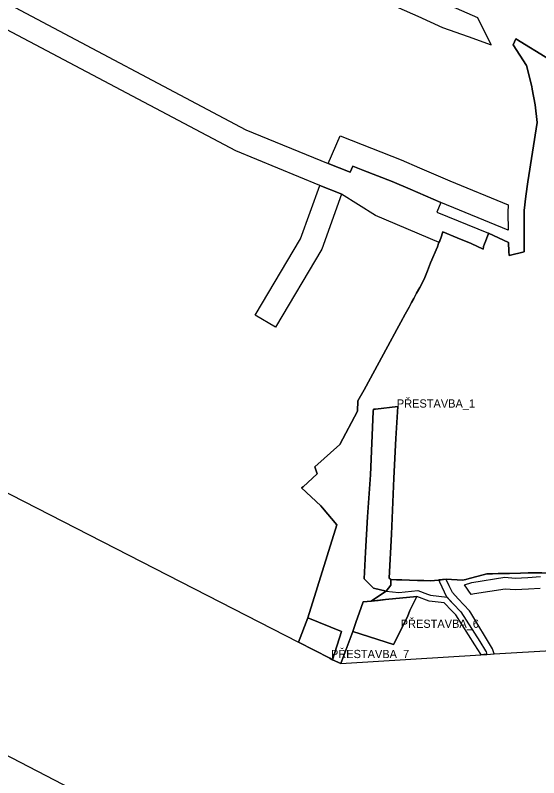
# Model space of a CAD drawing. Extents: x -521621 to -516761, y -1190184 to -1184927.
# Drawn here: x -520400 to -519954, y -1187593 to -1186944 of the extents above; entities that cross this region are included whole.
import ezdxf

# ---------------------------------------------------------------- set-up
doc = ezdxf.new("R2010")
doc.units = 0
for name, color, linetype in [('hran_SZUO_P-s', 7, 'Continuous'), ('HZU_P_s', 7, 'Continuous'), ('Implicitní', 7, 'Continuous'), ('prestavba_n', 7, 'Continuous'), ('zastavitelne plochy', 7, 'Continuous')]:
    doc.layers.add(name, color=color, linetype=linetype)

msp = doc.modelspace()

# ---------------------------------------------------------------- linework, layer by layer
at = {"layer": 'hran_SZUO_P-s'}
for points in [[(-519973.89, -1186964.34), (-519976.25, -1186969.59)], [(-519945.18, -1186982.09), (-519973.89, -1186964.34)], [(-519976.25, -1186969.59), (-519964.74, -1186987.19)], [(-519964.74, -1186987.19), (-519960.28, -1187004.95)], [(-519960.28, -1187004.95), (-519959.86, -1187007.38)], [(-519959.86, -1187007.38), (-519957.58, -1187020.75)], [(-519957.58, -1187020.75), (-519955.72, -1187035.72)], [(-519955.72, -1187035.72), (-519963.72, -1187086.02)], [(-519963.72, -1187086.02), (-519965.26, -1187098.25), (-519966.79, -1187110.48)], [(-519966.79, -1187110.48), (-519966.76, -1187125.1), (-519966.72, -1187139.73)], [(-520036.08, -1187128.81), (-520037.66, -1187134.14)], [(-520023.97, -1187133.79), (-520036.08, -1187128.81)], [(-519997.52, -1187130.94), (-519998.64, -1187133.89), (-519999.75, -1187136.84)], [(-519997.15, -1187129.97), (-519997.34, -1187130.46), (-519997.52, -1187130.94)], [(-519980.11, -1187137.79), (-519988.63, -1187133.88), (-519997.15, -1187129.97)], [(-520039.62, -1187138.78), (-520040.71, -1187141.36)], [(-520037.66, -1187134.14), (-520039.62, -1187138.78)], [(-520011.85, -1187138.77), (-520023.97, -1187133.79)], [(-520001.85, -1187143.49), (-520011.85, -1187138.77)], [(-519999.75, -1187136.84), (-520000.58, -1187139.01), (-520001.4, -1187141.18)], [(-519979.8, -1187145.46), (-519980.11, -1187137.79)], [(-519966.72, -1187139.73), (-519966.71, -1187142.68), (-519966.7, -1187145.62)], [(-520041.85, -1187144.05), (-520045.46, -1187152.58)], [(-520040.71, -1187141.36), (-520041.85, -1187144.05)], [(-520001.4, -1187141.18), (-520001.85, -1187143.49)], [(-519979.66, -1187148.75), (-519979.8, -1187145.46)], [(-519966.7, -1187145.62), (-519979.66, -1187148.75)], [(-520045.46, -1187152.58), (-520046.54, -1187155.01)], [(-520046.54, -1187155.01), (-520049.24, -1187161.96)], [(-520049.24, -1187161.96), (-520051.52, -1187167.64)], [(-520052.48, -1187170.02), (-520055.75, -1187176.08)], [(-520051.52, -1187167.64), (-520052.48, -1187170.02)], [(-520055.75, -1187176.08), (-520058.38, -1187180.94)], [(-520060.79, -1187185.41), (-520062.6, -1187188.74)], [(-520058.38, -1187180.94), (-520060.79, -1187185.41)], [(-520062.6, -1187188.74), (-520064.75, -1187192.74)], [(-520064.75, -1187192.74), (-520068.02, -1187198.79)], [(-520068.02, -1187198.79), (-520071.75, -1187205.69)], [(-520071.75, -1187205.69), (-520075.16, -1187212)], [(-520075.16, -1187212), (-520082.78, -1187226.03)], [(-520082.78, -1187226.03), (-520103.06, -1187263.21)], [(-520103.06, -1187263.21), (-520108.49, -1187272.64)], [(-520108.49, -1187272.64), (-520108.69, -1187281.29)], [(-520108.69, -1187281.29), (-520123.82, -1187309.68)], [(-520123.82, -1187309.68), (-520145.11, -1187328.82)], [(-520143.11, -1187334.68), (-520154.87, -1187345.66)], [(-520145.11, -1187328.82), (-520143.11, -1187334.68)], [(-520154.87, -1187345.66), (-520156.34, -1187346.76)], [(-520156.34, -1187346.76), (-520139.86, -1187362)], [(-520139.86, -1187362), (-520138.59, -1187363.54)], [(-520138.59, -1187363.54), (-520126.44, -1187378.2)], [(-520126.44, -1187378.2), (-520151.11, -1187457.31)], [(-519969.88, -1187419.22), (-519963.38, -1187419.06), (-519956.87, -1187418.91)], [(-519956.87, -1187418.91), (-519951.65, -1187419.02), (-519946.42, -1187419.12)], [(-520080.41, -1187429.63), (-520080.26, -1187424.69)], [(-520080.26, -1187424.69), (-520075.65, -1187424.83), (-520071.03, -1187424.98)], [(-520071.03, -1187424.98), (-520064.4, -1187425.2), (-520057.77, -1187425.41)], [(-520057.77, -1187425.41), (-520052.12, -1187425.59), (-520046.46, -1187425.77)], [(-520046.46, -1187425.77), (-520039.87, -1187425.11)], [(-520039.87, -1187425.11), (-520033.27, -1187424.46)], [(-520033.27, -1187424.46), (-520019.29, -1187425.32)], [(-520019.29, -1187425.32), (-520016.5, -1187424.59)], [(-520016.5, -1187424.59), (-520013.71, -1187423.87)], [(-520013.71, -1187423.87), (-520006.09, -1187421.89), (-519998.46, -1187419.91)], [(-519998.46, -1187419.91), (-519993.68, -1187419.8), (-519988.89, -1187419.68)], [(-519988.89, -1187419.68), (-519979.39, -1187419.45), (-519969.88, -1187419.22)], [(-520084.35, -1187434.57), (-520080.41, -1187429.63)], [(-520090.73, -1187438.81), (-520084.35, -1187434.57)], [(-520097.11, -1187443.05), (-520090.73, -1187438.81)], [(-520084.9, -1187441.83), (-520091.01, -1187442.44), (-520097.11, -1187443.05)], [(-520058.07, -1187439.16), (-520084.9, -1187441.83)], [(-520064.09, -1187451.2), (-520058.07, -1187439.16)], [(-520066.25, -1187456.45), (-520064.09, -1187451.2)], [(-520151.11, -1187457.31), (-520159, -1187477.9)], [(-520077.97, -1187480.04), (-520066.25, -1187456.45)], [(-520113.63, -1187471.26), (-520112.8, -1187468.95)], [(-520112.8, -1187468.95), (-520077.97, -1187480.04)], [(-520122.89, -1187496.11), (-520113.63, -1187471.26)], [(-520159, -1187477.9), (-520132.3, -1187491.79)], [(-520132.3, -1187491.79), (-520129.99, -1187493.02)], [(-520129.99, -1187493.02), (-520122.89, -1187496.11)]]:
    msp.add_lwpolyline(points, dxfattribs=at)
at = {"layer": 'HZU_P_s'}
for p, q in [((-519976.25, -1186969.59), (-519973.89, -1186964.34)), ((-519973.89, -1186964.34), (-519945.18, -1186982.09)), ((-519964.74, -1186987.19), (-519976.25, -1186969.59)), ((-519960.28, -1187004.95), (-519964.74, -1186987.19)), ((-519959.86, -1187007.38), (-519960.28, -1187004.95)), ((-519957.58, -1187020.75), (-519959.86, -1187007.38)), ((-519955.72, -1187035.72), (-519957.58, -1187020.75)), ((-519963.72, -1187086.02), (-519955.72, -1187035.72)), ((-519965.26, -1187098.25), (-519963.72, -1187086.02)), ((-519966.79, -1187110.48), (-519965.26, -1187098.25)), ((-520037.66, -1187134.14), (-520036.08, -1187128.81)), ((-520040.71, -1187141.36), (-520039.62, -1187138.78)), ((-520039.62, -1187138.78), (-520037.66, -1187134.14)), ((-520045.46, -1187152.58), (-520041.85, -1187144.05)), ((-520041.85, -1187144.05), (-520040.71, -1187141.36)), ((-520046.54, -1187155.01), (-520045.46, -1187152.58)), ((-520049.24, -1187161.96), (-520046.54, -1187155.01)), ((-520051.52, -1187167.64), (-520049.24, -1187161.96)), ((-520055.75, -1187176.08), (-520052.48, -1187170.02)), ((-520052.48, -1187170.02), (-520051.52, -1187167.64)), ((-520058.38, -1187180.94), (-520055.75, -1187176.08)), ((-520062.6, -1187188.74), (-520060.79, -1187185.41)), ((-520060.79, -1187185.41), (-520058.38, -1187180.94)), ((-520064.75, -1187192.74), (-520062.6, -1187188.74)), ((-520068.02, -1187198.79), (-520064.75, -1187192.74)), ((-520071.75, -1187205.69), (-520068.02, -1187198.79)), ((-520075.16, -1187212), (-520071.75, -1187205.69)), ((-520082.78, -1187226.03), (-520075.16, -1187212)), ((-520103.06, -1187263.21), (-520082.78, -1187226.03)), ((-520108.49, -1187272.64), (-520103.06, -1187263.21)), ((-520108.69, -1187281.29), (-520108.49, -1187272.64)), ((-520123.82, -1187309.68), (-520108.69, -1187281.29)), ((-520145.11, -1187328.82), (-520123.82, -1187309.68)), ((-520154.87, -1187345.66), (-520143.11, -1187334.68)), ((-520143.11, -1187334.68), (-520145.11, -1187328.82)), ((-520156.34, -1187346.76), (-520154.87, -1187345.66)), ((-520139.86, -1187362), (-520156.34, -1187346.76)), ((-520138.59, -1187363.54), (-520139.86, -1187362)), ((-520126.44, -1187378.2), (-520138.59, -1187363.54)), ((-520151.11, -1187457.31), (-520126.44, -1187378.2)), ((-519963.38, -1187419.06), (-519969.88, -1187419.22)), ((-519956.87, -1187418.91), (-519963.38, -1187419.06)), ((-519951.65, -1187419.02), (-519956.87, -1187418.91)), ((-520080.26, -1187424.69), (-520080.41, -1187429.63)), ((-520075.65, -1187424.83), (-520080.26, -1187424.69)), ((-520071.03, -1187424.98), (-520075.65, -1187424.83)), ((-520064.4, -1187425.2), (-520071.03, -1187424.98)), ((-520057.77, -1187425.41), (-520064.4, -1187425.2)), ((-520052.12, -1187425.59), (-520057.77, -1187425.41)), ((-520046.46, -1187425.77), (-520052.12, -1187425.59)), ((-520039.87, -1187425.11), (-520046.46, -1187425.77)), ((-520033.27, -1187424.46), (-520039.87, -1187425.11)), ((-520019.29, -1187425.32), (-520033.27, -1187424.46)), ((-520016.5, -1187424.59), (-520019.29, -1187425.32)), ((-520013.71, -1187423.87), (-520016.5, -1187424.59)), ((-520006.09, -1187421.89), (-520013.71, -1187423.87)), ((-519998.46, -1187419.91), (-520006.09, -1187421.89)), ((-519993.68, -1187419.8), (-519998.46, -1187419.91)), ((-519988.89, -1187419.68), (-519993.68, -1187419.8)), ((-519979.39, -1187419.45), (-519988.89, -1187419.68)), ((-519969.88, -1187419.22), (-519979.39, -1187419.45)), ((-520080.41, -1187429.63), (-520084.35, -1187434.57)), ((-520084.9, -1187441.83), (-520058.07, -1187439.16)), ((-520058.07, -1187439.16), (-520064.09, -1187451.2)), ((-520064.09, -1187451.2), (-520066.25, -1187456.45)), ((-520159, -1187477.9), (-520151.11, -1187457.31)), ((-520066.25, -1187456.45), (-520077.97, -1187480.04)), ((-520112.8, -1187468.95), (-520113.63, -1187471.26)), ((-520077.97, -1187480.04), (-520112.8, -1187468.95)), ((-520113.63, -1187471.26), (-520122.89, -1187496.11)), ((-520132.3, -1187491.79), (-520159, -1187477.9)), ((-520129.99, -1187493.02), (-520132.3, -1187491.79)), ((-520122.89, -1187496.11), (-520129.99, -1187493.02))]:
    msp.add_line(p, q, dxfattribs=at)
for points in [[(-519966.72, -1187139.73), (-519966.76, -1187125.1), (-519966.79, -1187110.48)], [(-520036.08, -1187128.81), (-520023.97, -1187133.79)], [(-519999.75, -1187136.84), (-519998.64, -1187133.89), (-519997.52, -1187130.94)], [(-519997.52, -1187130.94), (-519997.34, -1187130.46), (-519997.15, -1187129.97)], [(-519997.15, -1187129.97), (-519988.63, -1187133.88), (-519980.11, -1187137.79)], [(-520023.97, -1187133.79), (-520011.85, -1187138.77)], [(-520011.85, -1187138.77), (-520001.85, -1187143.49)], [(-520001.4, -1187141.18), (-520000.58, -1187139.01), (-519999.75, -1187136.84)], [(-519980.11, -1187137.79), (-519979.8, -1187145.46)], [(-519966.7, -1187145.62), (-519966.71, -1187142.68), (-519966.72, -1187139.73)], [(-520001.85, -1187143.49), (-520001.4, -1187141.18)], [(-519979.8, -1187145.46), (-519979.66, -1187148.75)], [(-519979.66, -1187148.75), (-519966.7, -1187145.62)], [(-520084.35, -1187434.57), (-520090.73, -1187438.81), (-520097.11, -1187443.05)], [(-520097.11, -1187443.05), (-520091.01, -1187442.44), (-520084.9, -1187441.83)]]:
    msp.add_lwpolyline(points, dxfattribs=at)
at = {"layer": 'Implicitní'}
for p, q in [((-520133.61, -1187070.63), (-520123.44, -1187047.07)), ((-520123.44, -1187047.07), (-520104.81, -1187054.38)), ((-520104.81, -1187054.38), (-520096.76, -1187057.54)), ((-520096.76, -1187057.54), (-520071.63, -1187067.45)), ((-520071.63, -1187067.45), (-520056, -1187074.11)), ((-520114.98, -1187077.93), (-520133.61, -1187070.63)), ((-520112.74, -1187072.75), (-520114.98, -1187077.93)), ((-520104.09, -1187076.15), (-520112.74, -1187072.75)), ((-520056, -1187074.11), (-520029.96, -1187085.21)), ((-520079.22, -1187085.96), (-520104.09, -1187076.15)), ((-520063.84, -1187092.51), (-520079.22, -1187085.96)), ((-520029.96, -1187085.21), (-519980.3, -1187105.65)), ((-520157.3, -1187134.81), (-520140.91, -1187089.25)), ((-520140.91, -1187089.25), (-520123.45, -1187096.09)), ((-520037.69, -1187103.65), (-520063.84, -1187092.51)), ((-520122.36, -1187096.77), (-520139.13, -1187143.38)), ((-520123.45, -1187096.09), (-520122.36, -1187096.77)), ((-519980.34, -1187127.26), (-520037.69, -1187103.65)), ((-519980.3, -1187105.65), (-519980.67, -1187112.17)), ((-519980.67, -1187112.17), (-519980.34, -1187127.26)), ((-520195.74, -1187199.54), (-520157.3, -1187134.81)), ((-520139.13, -1187143.38), (-520178.54, -1187209.75)), ((-520178.54, -1187209.75), (-520195.74, -1187199.54)), ((-520097.7, -1187335.57), (-520095.26, -1187281.75)), ((-520095.26, -1187281.75), (-520094.96, -1187279.59)), ((-520094.96, -1187279.59), (-520093.26, -1187279.59)), ((-520093.26, -1187279.59), (-520074.47, -1187277.44)), ((-520074.47, -1187277.44), (-520075.98, -1187304.68)), ((-520075.98, -1187304.68), (-520077.74, -1187338.31)), ((-520471.93, -1187317.54), (-520159, -1187477.9)), ((-520100.32, -1187371.37), (-520097.7, -1187335.57)), ((-520077.74, -1187338.31), (-520079.87, -1187386.04)), ((-520101.79, -1187401.47), (-520100.32, -1187371.37)), ((-520079.87, -1187386.04), (-520081.88, -1187423.69)), ((-520103.02, -1187424.15), (-520101.79, -1187401.47)), ((-520095.15, -1187432.18), (-520103.02, -1187424.15)), ((-520081.88, -1187423.69), (-520080.26, -1187424.69)), ((-520080.26, -1187424.69), (-520080.41, -1187429.63)), ((-520011.47, -1187427.12), (-519983.23, -1187422.8)), ((-519983.23, -1187422.8), (-519974.43, -1187423.57)), ((-519974.43, -1187423.57), (-519963.63, -1187422.96)), ((-519963.63, -1187422.96), (-519952.98, -1187422.19)), ((-520084.35, -1187434.57), (-520095.15, -1187432.18)), ((-520080.41, -1187429.63), (-520084.35, -1187434.57)), ((-519982.91, -1187432.87), (-520009.06, -1187436.87)), ((-519974.58, -1187433.59), (-519982.91, -1187432.87)), ((-519962.99, -1187432.94), (-519974.58, -1187433.59)), ((-519953.06, -1187432.22), (-519962.99, -1187432.94)), ((-520105.47, -1187448.5), (-520103.75, -1187443.71)), ((-520103.75, -1187443.71), (-520097.11, -1187443.05)), ((-520097.11, -1187443.05), (-520091.01, -1187442.44)), ((-520091.01, -1187442.44), (-520084.9, -1187441.83)), ((-520084.9, -1187441.83), (-520058.07, -1187439.16)), ((-520058.07, -1187439.16), (-520064.09, -1187451.2)), ((-520110.1, -1187461.43), (-520105.47, -1187448.5)), ((-520064.09, -1187451.2), (-520066.25, -1187456.45)), ((-520159, -1187477.9), (-520151.11, -1187457.31)), ((-520151.11, -1187457.31), (-520122.23, -1187468.86)), ((-520066.25, -1187456.45), (-520077.97, -1187480.04)), ((-520112.8, -1187468.95), (-520110.1, -1187461.43)), ((-520122.23, -1187468.86), (-520129.99, -1187493.02)), ((-520077.97, -1187480.04), (-520112.8, -1187468.95)), ((-520159, -1187477.9), (-520132.3, -1187491.79)), ((-520132.3, -1187491.79), (-520159, -1187477.9)), ((-519992.26, -1187488.06), (-519891.6, -1187481.86)), ((-520063.27, -1187492.44), (-520003.64, -1187488.76)), ((-520003.64, -1187488.76), (-520001.06, -1187488.6)), ((-520001.06, -1187488.6), (-519998.47, -1187488.44)), ((-519998.47, -1187488.44), (-519995.37, -1187488.25)), ((-519995.37, -1187488.25), (-519992.26, -1187488.06)), ((-520132.3, -1187491.79), (-520131.15, -1187492.41)), ((-520131.15, -1187492.41), (-520132.3, -1187491.79)), ((-520131.15, -1187492.41), (-520129.99, -1187493.02)), ((-520129.99, -1187493.02), (-520131.15, -1187492.41)), ((-520129.99, -1187493.02), (-520122.89, -1187496.11)), ((-520122.89, -1187496.11), (-520063.27, -1187492.44))]:
    msp.add_line(p, q, dxfattribs=at)
for points in [[(-520000.58, -1187139.01), (-520001.4, -1187141.18), (-520001.85, -1187143.49), (-520011.85, -1187138.77), (-520023.97, -1187133.79), (-520036.08, -1187128.81), (-520037.66, -1187134.14), (-520039.2, -1187137.79), (-520093.34, -1187114.72), (-520122.36, -1187096.77), (-520123.45, -1187096.09), (-520140.91, -1187089.25), (-520212.35, -1187059.89), (-520412.35, -1186953.84), (-520504.6, -1186929.09), (-520687.3, -1186869.51), (-520687.42, -1186853.11), (-520687.55, -1186835.51), (-520687.59, -1186830.55), (-520687.63, -1186824.51), (-520687.76, -1186806.97), (-520687.95, -1186781.61), (-520688.25, -1186740.46), (-520673.2, -1186654.79)], [(-520654.76, -1186665.44), (-520667.77, -1186739.45), (-520667.43, -1186850.56), (-520667.41, -1186854.96), (-520498.9, -1186909.91), (-520404.98, -1186935.11), (-520203.84, -1187041.77), (-520133.61, -1187070.63), (-520114.98, -1187077.93), (-520112.74, -1187072.75), (-520104.09, -1187076.15), (-520079.22, -1187085.96), (-520063.84, -1187092.51), (-520037.69, -1187103.65), (-520041.14, -1187111.86), (-519997.15, -1187129.97), (-519997.34, -1187130.46), (-519997.52, -1187130.94), (-519998.46, -1187133.42), (-519998.64, -1187133.89), (-519999.75, -1187136.84), (-520000.58, -1187139.01)], [(-519963.31, -1187658.97), (-520250.83, -1187655.58), (-520830.3, -1187354.88)], [(-520009.06, -1187436.87), (-520012.04, -1187437.34), (-520017.52, -1187429.25), (-520011.47, -1187427.12)], [(-520028.41, -1187451.33), (-520034.9, -1187444.46), (-520047.58, -1187443.02), (-520058.07, -1187439.16), (-520084.9, -1187441.83), (-520097.11, -1187443.05), (-520084.35, -1187434.57), (-520073.6, -1187435.68), (-520057.42, -1187434.07), (-520049.22, -1187437.09), (-520046.42, -1187438.12), (-520032.51, -1187439.69), (-520027.25, -1187445.29), (-520020.79, -1187452.11)], [(-520001.06, -1187488.6), (-520003.64, -1187488.76), (-520003.78, -1187488.36), (-520008.9, -1187480.27), (-520025.01, -1187454.78), (-520028.41, -1187451.33)], [(-520020.79, -1187452.11), (-520004.67, -1187477.59), (-519999.7, -1187485.45), (-519999.23, -1187486.19), (-519998.47, -1187488.44), (-520001.06, -1187488.6)]]:
    msp.add_lwpolyline(points, dxfattribs=at)
at = {"layer": 'prestavba_n'}
for points in [[(-520093.26, -1187279.59), (-520094.96, -1187279.59), (-520095.26, -1187281.75), (-520097.7, -1187335.57), (-520100.32, -1187371.37), (-520101.79, -1187401.47), (-520103.02, -1187424.15), (-520095.15, -1187432.18), (-520084.35, -1187434.57), (-520080.41, -1187429.63), (-520080.26, -1187424.69), (-520081.88, -1187423.69), (-520079.87, -1187386.04), (-520077.74, -1187338.31), (-520075.98, -1187304.68), (-520074.47, -1187277.44), (-520093.26, -1187279.59)], [(-520091.01, -1187442.44), (-520097.11, -1187443.05), (-520103.75, -1187443.71), (-520105.47, -1187448.5), (-520110.1, -1187461.43), (-520112.8, -1187468.95), (-520077.97, -1187480.04), (-520066.25, -1187456.45), (-520064.09, -1187451.2), (-520058.07, -1187439.16), (-520084.9, -1187441.83), (-520091.01, -1187442.44)], [(-520131.15, -1187492.41), (-520129.99, -1187493.02), (-520122.23, -1187468.86), (-520151.11, -1187457.31), (-520159, -1187477.9), (-520132.3, -1187491.79), (-520131.15, -1187492.41)]]:
    msp.add_lwpolyline(points, dxfattribs=at)
at = {"layer": 'zastavitelne plochy'}
for points in [[(-520129.23, -1186913.42), (-520057.44, -1186945.19), (-520036.32, -1186954.86), (-520014.58, -1186962.43), (-519994.79, -1186969.47), (-520006.39, -1186946.62), (-520132.95, -1186890.9), (-520241.59, -1186842.91), (-520374.47, -1186784.03), (-520377.11, -1186789.47), (-520380.62, -1186787.87), (-520385.2, -1186791.58), (-520396.27, -1186799.32), (-520387.78, -1186801.36), (-520312.71, -1186833.98), (-520220.95, -1186873.71), (-520129.23, -1186913.42)], [(-520039.4, -1187425.07), (-520038.84, -1187426.72), (-520032.88, -1187439.3), (-520027.25, -1187445.29), (-520020.79, -1187452.11), (-520004.67, -1187477.59), (-519999.7, -1187485.45), (-519999.23, -1187486.19), (-519998.47, -1187488.44), (-519995.37, -1187488.25), (-519992.26, -1187488.06), (-519993.76, -1187483.65), (-520012.27, -1187452.98), (-520013.28, -1187451.31), (-520022.89, -1187441.17), (-520027.86, -1187435.88), (-520030.66, -1187429.97), (-520032.95, -1187425.14), (-520032.96, -1187425.12), (-520033.18, -1187424.47), (-520033.27, -1187424.46), (-520039.4, -1187425.07)]]:
    msp.add_lwpolyline(points, dxfattribs=at)

# ---------------------------------------------------------------- texts
at = {"layer": 'prestavba_n'}
for s, p in [('PŘESTAVBA_1', (-520075.22, -1187278.36)), ('PŘESTAVBA_6', (-520071.92, -1187465.84)), ('PŘESTAVBA_7', (-520131.3, -1187491.59))]:
    msp.add_text(s, height=7, dxfattribs=at).set_placement(p)

doc.saveas('drawing.dxf')
